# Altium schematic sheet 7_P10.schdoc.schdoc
size 309 x 223 mm; Symbol: A4_Schematic_0605; Device: A4_Schematic_0605; @Project Name: MDIO-Board_Rev_01(0124); @Page Count: 10; @Update Date: 2024-05-25; @Create Date: 2024-05-20; @Schematic Name: Schematic1; @Page No: 10; @Page Name: P10
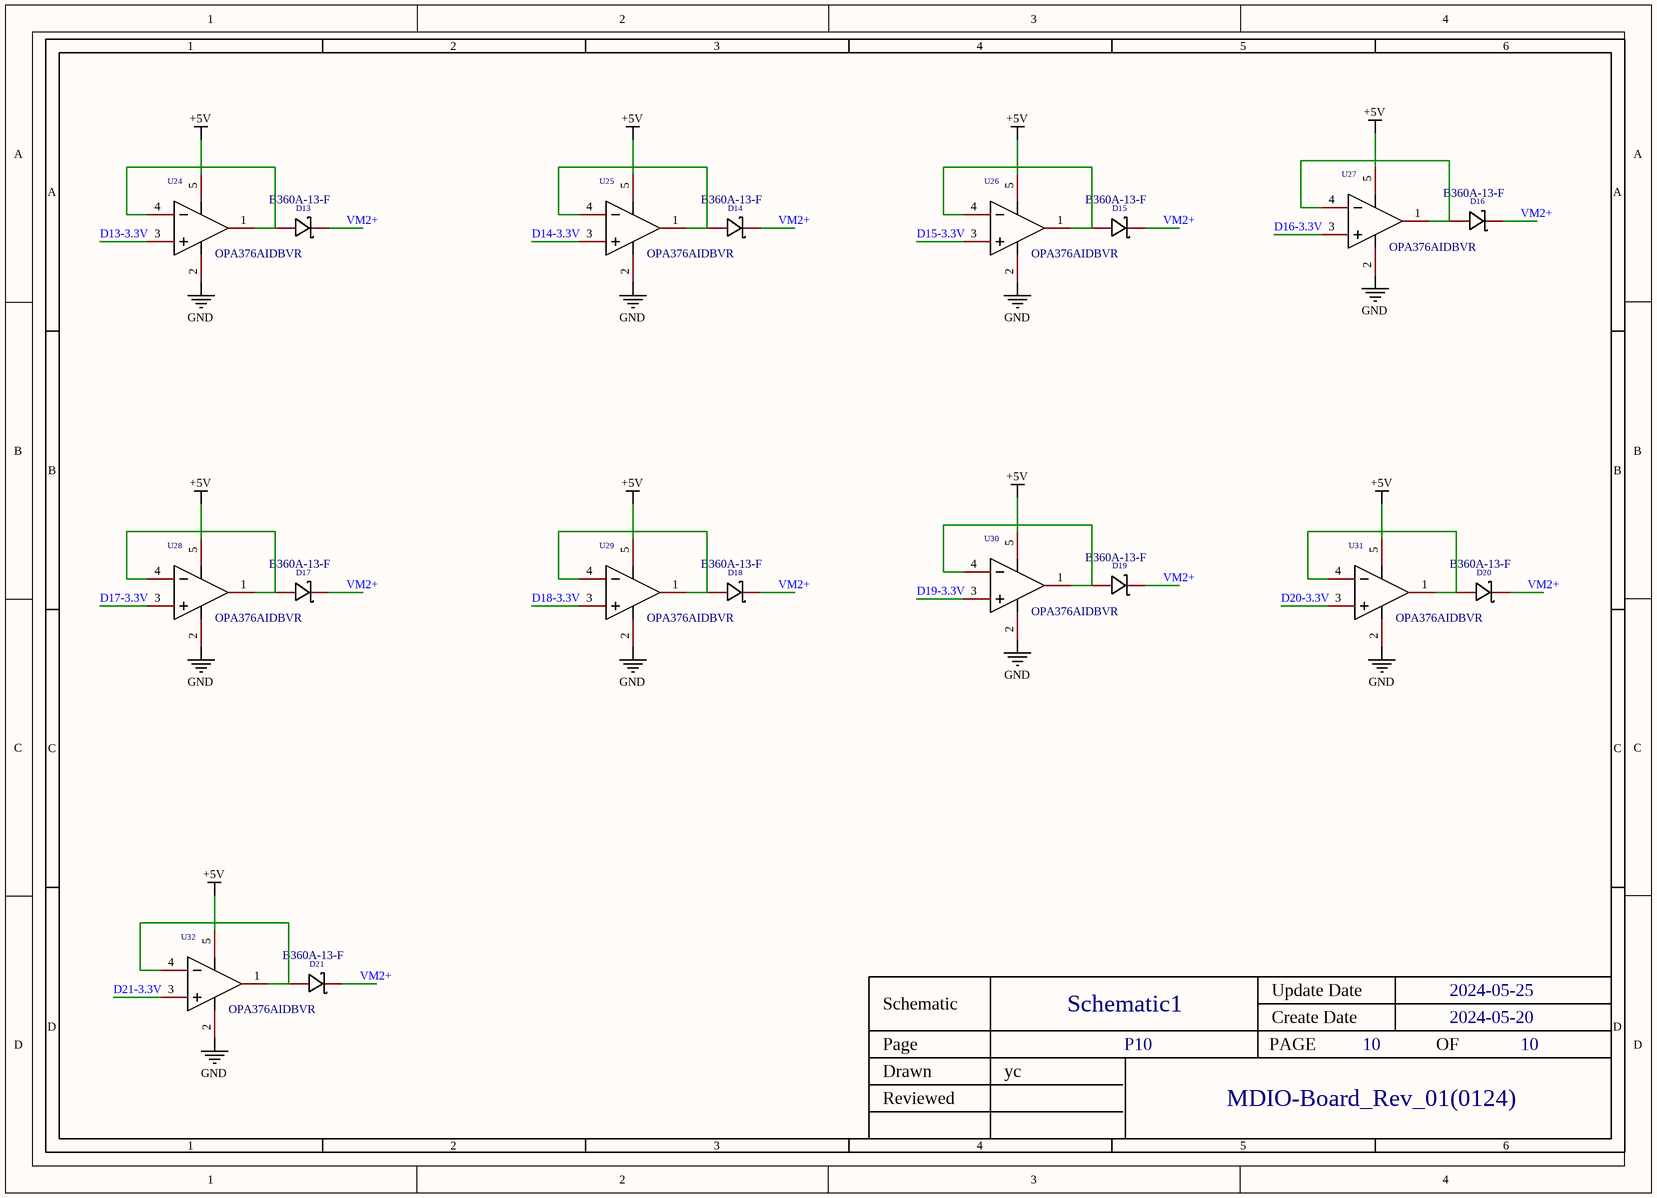
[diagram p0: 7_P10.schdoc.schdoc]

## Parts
D13  B360A-13-F  [SMA_L4.4-W2.6-LS5.0-RD]
D14  B360A-13-F  [SMA_L4.4-W2.6-LS5.0-RD]
D15  B360A-13-F  [SMA_L4.4-W2.6-LS5.0-RD]
D16  B360A-13-F  [SMA_L4.4-W2.6-LS5.0-RD]
D17  B360A-13-F  [SMA_L4.4-W2.6-LS5.0-RD]
D18  B360A-13-F  [SMA_L4.4-W2.6-LS5.0-RD]
D19  B360A-13-F  [SMA_L4.4-W2.6-LS5.0-RD]
D20  B360A-13-F  [SMA_L4.4-W2.6-LS5.0-RD]
D21  B360A-13-F  [SMA_L4.4-W2.6-LS5.0-RD]
U24  OPA376AIDBVR  [SOT-23-5_L3.0-W1.7-P0.95-LS2.8-BR]
U25  OPA376AIDBVR  [SOT-23-5_L3.0-W1.7-P0.95-LS2.8-BR]
U26  OPA376AIDBVR  [SOT-23-5_L3.0-W1.7-P0.95-LS2.8-BR]
U27  OPA376AIDBVR  [SOT-23-5_L3.0-W1.7-P0.95-LS2.8-BR]
U28  OPA376AIDBVR  [SOT-23-5_L3.0-W1.7-P0.95-LS2.8-BR]
U29  OPA376AIDBVR  [SOT-23-5_L3.0-W1.7-P0.95-LS2.8-BR]
U30  OPA376AIDBVR  [SOT-23-5_L3.0-W1.7-P0.95-LS2.8-BR]
U31  OPA376AIDBVR  [SOT-23-5_L3.0-W1.7-P0.95-LS2.8-BR]
U32  OPA376AIDBVR  [SOT-23-5_L3.0-W1.7-P0.95-LS2.8-BR]

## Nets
+5V: U24.5(V+) U25.5(V+) U26.5(V+) U27.5(V+) U28.5(V+) U29.5(V+) U30.5(V+) U31.5(V+) U32.5(V+)
GND: U24.2(V-) U25.2(V-) U26.2(V-) U27.2(V-) U28.2(V-) U29.2(V-) U30.2(V-) U31.2(V-) U32.2(V-)
D13-3.3V: U24.3(IN+)
D14-3.3V: U25.3(IN+)
D15-3.3V: U26.3(IN+)
D16-3.3V: U27.3(IN+)
D17-3.3V: U28.3(IN+)
D18-3.3V: U29.3(IN+)
D19-3.3V: U30.3(IN+)
D20-3.3V: U31.3(IN+)
D21-3.3V: U32.3(IN+)
VM2+: D13.1(K) D14.1(K) D15.1(K) D16.1(K) D17.1(K) D18.1(K) D19.1(K) D20.1(K) D21.1(K)
NetD13_2: D13.2(A) U24.1(OUT) U24.4(IN-)
NetD14_2: D14.2(A) U25.1(OUT) U25.4(IN-)
NetD15_2: D15.2(A) U26.1(OUT) U26.4(IN-)
NetD16_2: D16.2(A) U27.1(OUT) U27.4(IN-)
NetD17_2: D17.2(A) U28.1(OUT) U28.4(IN-)
NetD18_2: D18.2(A) U29.1(OUT) U29.4(IN-)
NetD19_2: D19.2(A) U30.1(OUT) U30.4(IN-)
NetD20_2: D20.2(A) U31.1(OUT) U31.4(IN-)
NetD21_2: D21.2(A) U32.1(OUT) U32.4(IN-)

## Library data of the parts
D13-D21 = B360A-13-F: Manufacturer: DIODES(美台); Add into BOM: yes; Forward Voltage (Vf@If): 700mV@3A; Reverse Voltage (Vr): 60V; Average Rectified Current (Io): 3A; Reverse Leakage Current (Ir): 500uA@60V; Description: Forward Voltage (Vf@If):700mV@3A Reverse Voltage (Vr):60V Average Rectified Current (Io):3A Reverse Leakage Current (Ir):500uA@60V
U24-U32 = OPA376AIDBVR: Manufacturer: TI(德州仪器); Add into BOM: yes; Number of Circuits: 单路; Gain Bandwidth Product(GBP): 5.5MHz; Current - Input Bias(Ib): 0.2pA; Slew Rate(SR): 2V/us; Output Current: 50mA; Supply Current: 760uA; Description: Number of Circuits:单路 Gain Bandwidth Product(GBP):5.5MHz Current - Input Bias(Ib):0.2pA Slew Rate(SR):2V/us Output Current:50mA Output Type:- Rail to Rail:- Supply Current:760uA Operating Temperature:-40℃~+125℃ Operating Temperature:-40℃~+125℃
